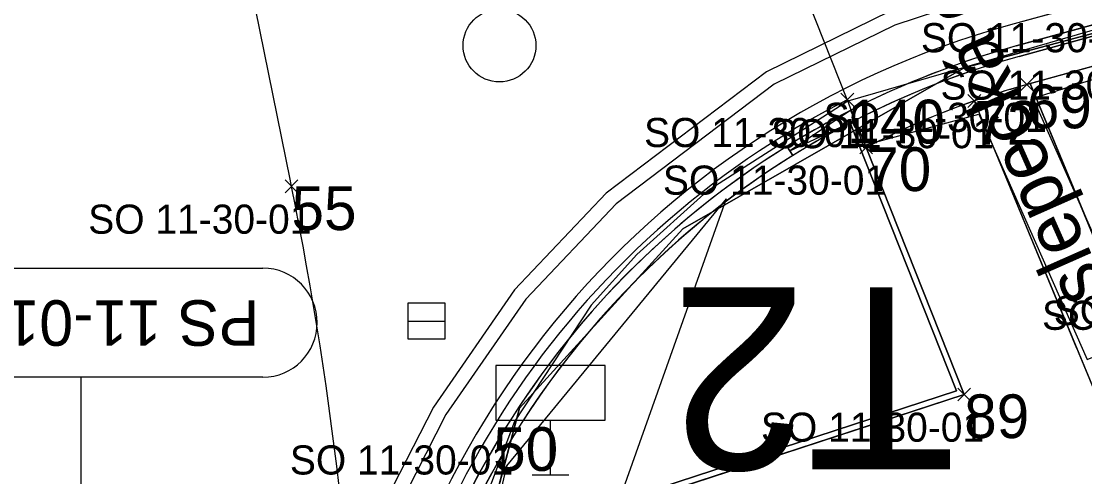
# Model space of a CAD drawing. Extents: x -728800 to -728100, y -1073200 to -1072700.
# Drawn here: x -728506.62 to -728492.02, y -1073033.55 to -1073027.3 of the extents above; entities that cross this region are included whole.
import ezdxf

# ---------------------------------------------------------------- set-up
doc = ezdxf.new("R2010")
doc.units = 0
for name, color, linetype in [('_NOR-návrh tenká', 7, 'Continuous'), ('_NOR-VDZ', 7, 'Continuous'), ('_NOR-šraf_+-0', 7, 'Continuous'), ('_NOR-šraf_+12', 7, 'Continuous'), ('_NOR-šraf_bezbariéra', 7, 'Continuous'), ('_NOR-šraf_chodník', 7, 'Continuous'), ('_NOR-šraf_signální pás', 7, 'Continuous'), ('_NOR-šraf_varovný pás', 7, 'Continuous'), ('_NOR-šraf_vozovka', 7, 'Continuous'), ('_NOR-šraf_zeleň', 7, 'Continuous'), ('A1_OBVOD Spravy železnic', 7, 'Continuous'), ('A2_OBVOD STAVBY', 7, 'Continuous'), ('B1_body_poloha', 7, 'Continuous'), ('B2_body_číslo', 7, 'Continuous'), ('B3_body_popiska', 7, 'Continuous'), ('B6_JŽM', 7, 'Continuous'), ('KTA_členění PS a SO', 7, 'Continuous'), ('ZA_01_Trvalý_pro_SŽDC_dle_UMVZST', 7, 'Continuous'), ('ZA_02_Dočasný_do_1_roku', 7, 'Continuous')]:
    doc.layers.add(name, color=color, linetype=linetype)

msp = doc.modelspace()

# ---------------------------------------------------------------- linework, layer by layer
at = {"layer": '_NOR-návrh tenká'}
for p, q in [((-728492.771, -1073028.155), (-728491.091, -1073032.219)), ((-728493.539, -1073028.392), (-728492.136, -1073031.786)), ((-728495.239, -1073028.523), (-728496.07, -1073029.079)), ((-728495.171, -1073028.656), (-728495.239, -1073028.523)), ((-728496.07, -1073029.079), (-728495.171, -1073028.656)), ((-728496.11, -1073029.015), (-728496.031, -1073029.142))]:
    msp.add_line(p, q, dxfattribs=at)
for points in [[(-728489.108, -1073026.574), (-728489.188, -1073026.285), (-728493.044, -1073027.348)], [(-728489.108, -1073026.574), (-728492.964, -1073027.637)], [(-728489.068, -1073026.719), (-728492.924, -1073027.782)], [(-728491.214, -1073027.725), (-728492.818, -1073028.168)], [(-728495.168, -1073028.664), (-728493.678, -1073032.423), (-728500.748, -1073034.736)], [(-728495.242, -1073028.693), (-728493.784, -1073032.373), (-728500.708, -1073034.638)]]:
    msp.add_lwpolyline(points, dxfattribs=at)
for radius, end in [(12.3, 176.1779), (12, 176.2645), (11.85, 176.3095), (11.45, 117.2893)]:
    msp.add_arc((-728489.773, -1073039.206), radius, 105.42, end, dxfattribs=at)
at = {"layer": '_NOR-VDZ'}
msp.add_lwpolyline([(-728502.909, -1073029.566), (-728502.929, -1073029.468), (-728506.181, -1073013.442)], dxfattribs=at)
for centre, radius, start, end in [((-728489.773, -1073039.206), 12.15, 116.9619, 176.2207), ((-728551.773, -1073039.431), 49.85, 1.1854, 11.4145)]:
    msp.add_arc(centre, radius, start, end, dxfattribs=at)
at = {"layer": '_NOR-šraf_+-0'}
for points in [[(-728495.171, -1073028.656), (-728495.023, -1073029.03), (-728493.678, -1073032.423), (-728500.748, -1073034.736)], [(-728500.708, -1073034.638), (-728493.784, -1073032.373), (-728495.242, -1073028.693)]]:
    msp.add_lwpolyline(points, dxfattribs=at)
msp.add_arc((-728489.773, -1073039.206), 11.85, 117.0974, 117.4861, dxfattribs=at)
at = {"layer": '_NOR-šraf_+12'}
for p, q in [((-728496.07, -1073029.079), (-728496.11, -1073029.015)), ((-728496.031, -1073029.142), (-728496.07, -1073029.079))]:
    msp.add_line(p, q, dxfattribs=at)
for radius, end in [(12, 176.2645), (11.85, 176.3095)]:
    msp.add_arc((-728489.773, -1073039.206), radius, 121.8734, end, dxfattribs=at)
at = {"layer": '_NOR-šraf_bezbariéra'}
for points in [[(-728492.924, -1073027.782), (-728491.368, -1073027.353), (-728491.408, -1073027.208), (-728492.964, -1073027.637)], [(-728495.239, -1073028.523), (-728495.171, -1073028.656), (-728495.171, -1073028.656)]]:
    msp.add_lwpolyline(points, dxfattribs=at)
for radius in [12, 11.85]:
    msp.add_arc((-728489.773, -1073039.206), radius, 105.42, 117.0974, dxfattribs=at)
at = {"layer": '_NOR-šraf_chodník'}
for p, q in [((-728493.539, -1073028.392), (-728491.352, -1073033.682)), ((-728493.678, -1073032.423), (-728495.023, -1073029.03)), ((-728498.439, -1073033.98), (-728493.678, -1073032.423))]:
    msp.add_line(p, q, dxfattribs=at)
msp.add_lwpolyline([(-728490.59, -1073033.433), (-728492.771, -1073028.155), (-728491.214, -1073027.725), (-728489.062, -1073032.933), (-728490.59, -1073033.433)], dxfattribs=at)
msp.add_arc((-728489.773, -1073039.206), 11.45, 109.1994, 117.2893, dxfattribs=at)
at = {"layer": '_NOR-šraf_signální pás'}
for points in [[(-728490.59, -1073033.433), (-728492.771, -1073028.155), (-728492.818, -1073028.168)], [(-728493.539, -1073028.392), (-728491.352, -1073033.682), (-728490.59, -1073033.433), (-728490.59, -1073033.433)]]:
    msp.add_lwpolyline(points, dxfattribs=at)
msp.add_arc((-728489.773, -1073039.206), 11.45, 105.42, 109.1994, dxfattribs=at)
at = {"layer": '_NOR-šraf_varovný pás'}
for points in [[(-728492.818, -1073028.168), (-728492.771, -1073028.155), (-728491.214, -1073027.725), (-728491.368, -1073027.353), (-728492.924, -1073027.782)], [(-728495.171, -1073028.656), (-728495.023, -1073029.03), (-728495.023, -1073029.03)]]:
    msp.add_lwpolyline(points, dxfattribs=at)
for radius, start, end in [(11.85, 105.42, 117.0974), (11.45, 105.42, 109.1994), (11.45, 109.1994, 117.2893)]:
    msp.add_arc((-728489.773, -1073039.206), radius, start, end, dxfattribs=at)
at = {"layer": '_NOR-šraf_vozovka'}
for p, q in [((-728489.188, -1073026.285), (-728493.044, -1073027.348)), ((-728492.964, -1073027.637), (-728491.408, -1073027.208))]:
    msp.add_line(p, q, dxfattribs=at)
for radius, start, end in [(12.3, 105.42, 176.1779), (12, 105.42, 117.0974), (12, 117.0974, 121.8734), (12, 121.8734, 176.2645)]:
    msp.add_arc((-728489.773, -1073039.206), radius, start, end, dxfattribs=at)
at = {"layer": '_NOR-šraf_zeleň'}
msp.add_lwpolyline([(-728495.242, -1073028.693), (-728493.784, -1073032.373), (-728500.708, -1073034.638)], dxfattribs=at)
for start, end in [(117.4861, 121.8734), (121.8734, 157.3304)]:
    msp.add_arc((-728489.773, -1073039.206), 11.85, start, end, dxfattribs=at)
at = {"layer": 'A1_OBVOD Spravy železnic'}
msp.add_lwpolyline([(-728503.24, -1073052.34), (-728501.946, -1073043.293), (-728501.19, -1073037.94), (-728499.78, -1073032.61), (-728497.54, -1073030.15), (-728493.68, -1073027.94), (-728443.97, -1073014.59), (-728443.68, -1073014.51), (-728441.09, -1073023.23), (-728428.92, -1073019.94), (-728429.82, -1073016.43), (-728427.49, -1073015.84), (-728421.24, -1073014.23), (-728422.34, -1073010.27), (-728422.77, -1073008.34), (-728418.21, -1073007), (-728380.57, -1072997.2), (-728343.1, -1072987.57), (-728330.49, -1072984.52), (-728326.79, -1072988.95)], dxfattribs=at)
at = {"layer": 'A2_OBVOD STAVBY'}
msp.add_lwpolyline([(-728488.873, -1073026.674), (-728489.181, -1073025.557), (-728493.185, -1073026.66), (-728494.705, -1073027.164), (-728496.389, -1073027.993), (-728498.589, -1073029.657), (-728499.85, -1073030.989), (-728500.962, -1073032.598), (-728501.8, -1073034.243), (-728502.009, -1073034.876), (-728501.833, -1073035.753)], dxfattribs=at)
at = {"layer": 'B1_body_poloha'}
for p, q in [((-728492.906, -1073028.08), (-728492.73, -1073028.256)), ((-728492.906, -1073028.256), (-728492.73, -1073028.08)), ((-728495.37, -1073028.288), (-728495.194, -1073028.464)), ((-728495.37, -1073028.464), (-728495.194, -1073028.288)), ((-728493.627, -1073028.304), (-728493.45, -1073028.481)), ((-728493.627, -1073028.481), (-728493.45, -1073028.304)), ((-728495.111, -1073028.942), (-728494.935, -1073029.118)), ((-728495.111, -1073029.118), (-728494.935, -1073028.942)), ((-728502.997, -1073029.477), (-728502.82, -1073029.654)), ((-728502.997, -1073029.654), (-728502.82, -1073029.477)), ((-728493.766, -1073032.335), (-728493.59, -1073032.511)), ((-728493.766, -1073032.511), (-728493.59, -1073032.335))]:
    msp.add_line(p, q, dxfattribs=at)
at = {"layer": 'B2_body_číslo'}
for p, q in [((-728492.818, -1073028.168), (-728492.818, -1073028.168)), ((-728495.282, -1073028.376), (-728495.282, -1073028.376)), ((-728493.539, -1073028.392), (-728493.539, -1073028.392)), ((-728495.023, -1073029.03), (-728495.023, -1073029.03)), ((-728502.909, -1073029.566), (-728502.909, -1073029.566)), ((-728493.678, -1073032.423), (-728493.678, -1073032.423)), ((-728500.142, -1073032.873), (-728500.142, -1073032.873))]:
    msp.add_line(p, q, dxfattribs=at)
at = {"layer": 'B6_JŽM'}
msp.add_line((-728499.605, -1073033.527), (-728499.105, -1073033.527), dxfattribs=at)
for points in [[(-728498.56, -1073020.107), (-728494.628, -1073019.466), (-728491.401, -1073027.273), (-728495.275, -1073028.394), (-728498.56, -1073020.107)], [(-728495.275, -1073028.394), (-728495.063, -1073029.004), (-728493.479, -1073028.573), (-728491.99, -1073031.943), (-728491.271, -1073031.657), (-728492.733, -1073028.355), (-728491.25, -1073027.888), (-728491.401, -1073027.273)], [(-728495.275, -1073028.394), (-728497.204, -1073029.633), (-728498.169, -1073030.501), (-728498.796, -1073031.198), (-728499.849, -1073032.794), (-728500.268, -1073033.914), (-728501.425, -1073038.634)], [(-728496.944, -1073029.737), (-728499.959, -1073033.406), (-728501.183, -1073038.706)], [(-728496.944, -1073029.737), (-728498.48, -1073034.066), (-728501.183, -1073038.706)], [(-728501.306, -1073031.416), (-728501.306, -1073031.166), (-728500.806, -1073031.166), (-728500.806, -1073031.666), (-728501.306, -1073031.666), (-728501.306, -1073031.416), (-728500.806, -1073031.416)], [(-728499.355, -1073033.527), (-728499.355, -1073032.777), (-728498.605, -1073032.777), (-728498.605, -1073032.027), (-728500.105, -1073032.027), (-728500.105, -1073032.777), (-728499.355, -1073032.777)]]:
    msp.add_lwpolyline(points, dxfattribs=at)
msp.add_circle((-728500.055, -1073027.632), 0.5, dxfattribs=at)
at = {"layer": 'KTA_členění PS a SO'}
msp.add_line((-728505.8, -1073032.188), (-728505.8, -1073036.528), dxfattribs=at)
for points in [[(-728508.3, -1073030.688), (-728503.3, -1073030.688)], [(-728503.3, -1073032.188), (-728508.3, -1073032.188)]]:
    msp.add_lwpolyline(points, dxfattribs=at)
msp.add_arc((-728503.306, -1073031.438), 0.75, 270.4529, 89.5471, dxfattribs=at)
at = {"layer": 'ZA_01_Trvalý_pro_SŽDC_dle_UMVZST'}
msp.add_lwpolyline([(-728500.719, -1073036.161), (-728501.19, -1073037.94), (-728493.84, -1073039.37), (-728493.51, -1073034.35), (-728488.39, -1073034.38), (-728491.302, -1073027.301), (-728493.68, -1073027.94), (-728497.54, -1073030.15), (-728499.78, -1073032.61)], close=True, dxfattribs=at)
at = {"layer": 'ZA_02_Dočasný_do_1_roku'}
msp.add_lwpolyline([(-728493.127, -1073026.851), (-728494.629, -1073027.35), (-728496.284, -1073028.164), (-728498.455, -1073029.806), (-728499.694, -1073031.116), (-728500.79, -1073032.701), (-728501.615, -1073034.32), (-728501.802, -1073034.888), (-728501.559, -1073036.1), (-728500.719, -1073036.161), (-728499.78, -1073032.61), (-728497.54, -1073030.15), (-728493.68, -1073027.94), (-728491.302, -1073027.301), (-728488.39, -1073034.38), (-728493.51, -1073034.35), (-728493.84, -1073039.37), (-728501.19, -1073037.94), (-728502.042, -1073043.972)], dxfattribs=at)

# ---------------------------------------------------------------- texts
at = {"layer": 'B2_body_číslo'}
for s, p in [('69', (-728492.818, -1073028.768)), ('140', (-728495.282, -1073028.976)), ('72', (-728493.539, -1073028.992)), ('70', (-728495.023, -1073029.63)), ('55', (-728502.909, -1073030.166)), ('89', (-728493.678, -1073033.023)), ('50', (-728500.142, -1073033.473))]:
    msp.add_text(s, height=0.6, dxfattribs=at).set_placement(p)
at = {"layer": 'B3_body_popiska'}
for p in [(-728494.272, -1073027.724), (-728494.003, -1073028.375), (-728495.607, -1073028.818), (-728498.071, -1073029.026), (-728496.328, -1073029.042), (-728497.812, -1073029.68), (-728505.698, -1073030.216), (-728492.61, -1073031.536), (-728492.449, -1073031.469), (-728496.467, -1073033.073), (-728502.931, -1073033.523)]:
    msp.add_text('SO 11-30-01', height=0.4, dxfattribs=at).set_placement(p)
at = {"layer": 'B6_JŽM'}
msp.add_text('slepecká dl ', height=0.75, rotation=113.8819, dxfattribs=at).set_placement((-728491.704, -1073031.002))
at = {"layer": 'KTA_členění PS a SO'}
msp.add_text('PS 11-01-31', height=0.625, rotation=180, dxfattribs=at).set_placement((-728503.35, -1073031.13))
at = {"layer": 'ZA_01_Trvalý_pro_SŽDC_dle_UMVZST'}
msp.add_text('T2', height=2.5, rotation=180, dxfattribs=at).set_placement((-728493.797, -1073030.953))

doc.saveas('drawing.dxf')
